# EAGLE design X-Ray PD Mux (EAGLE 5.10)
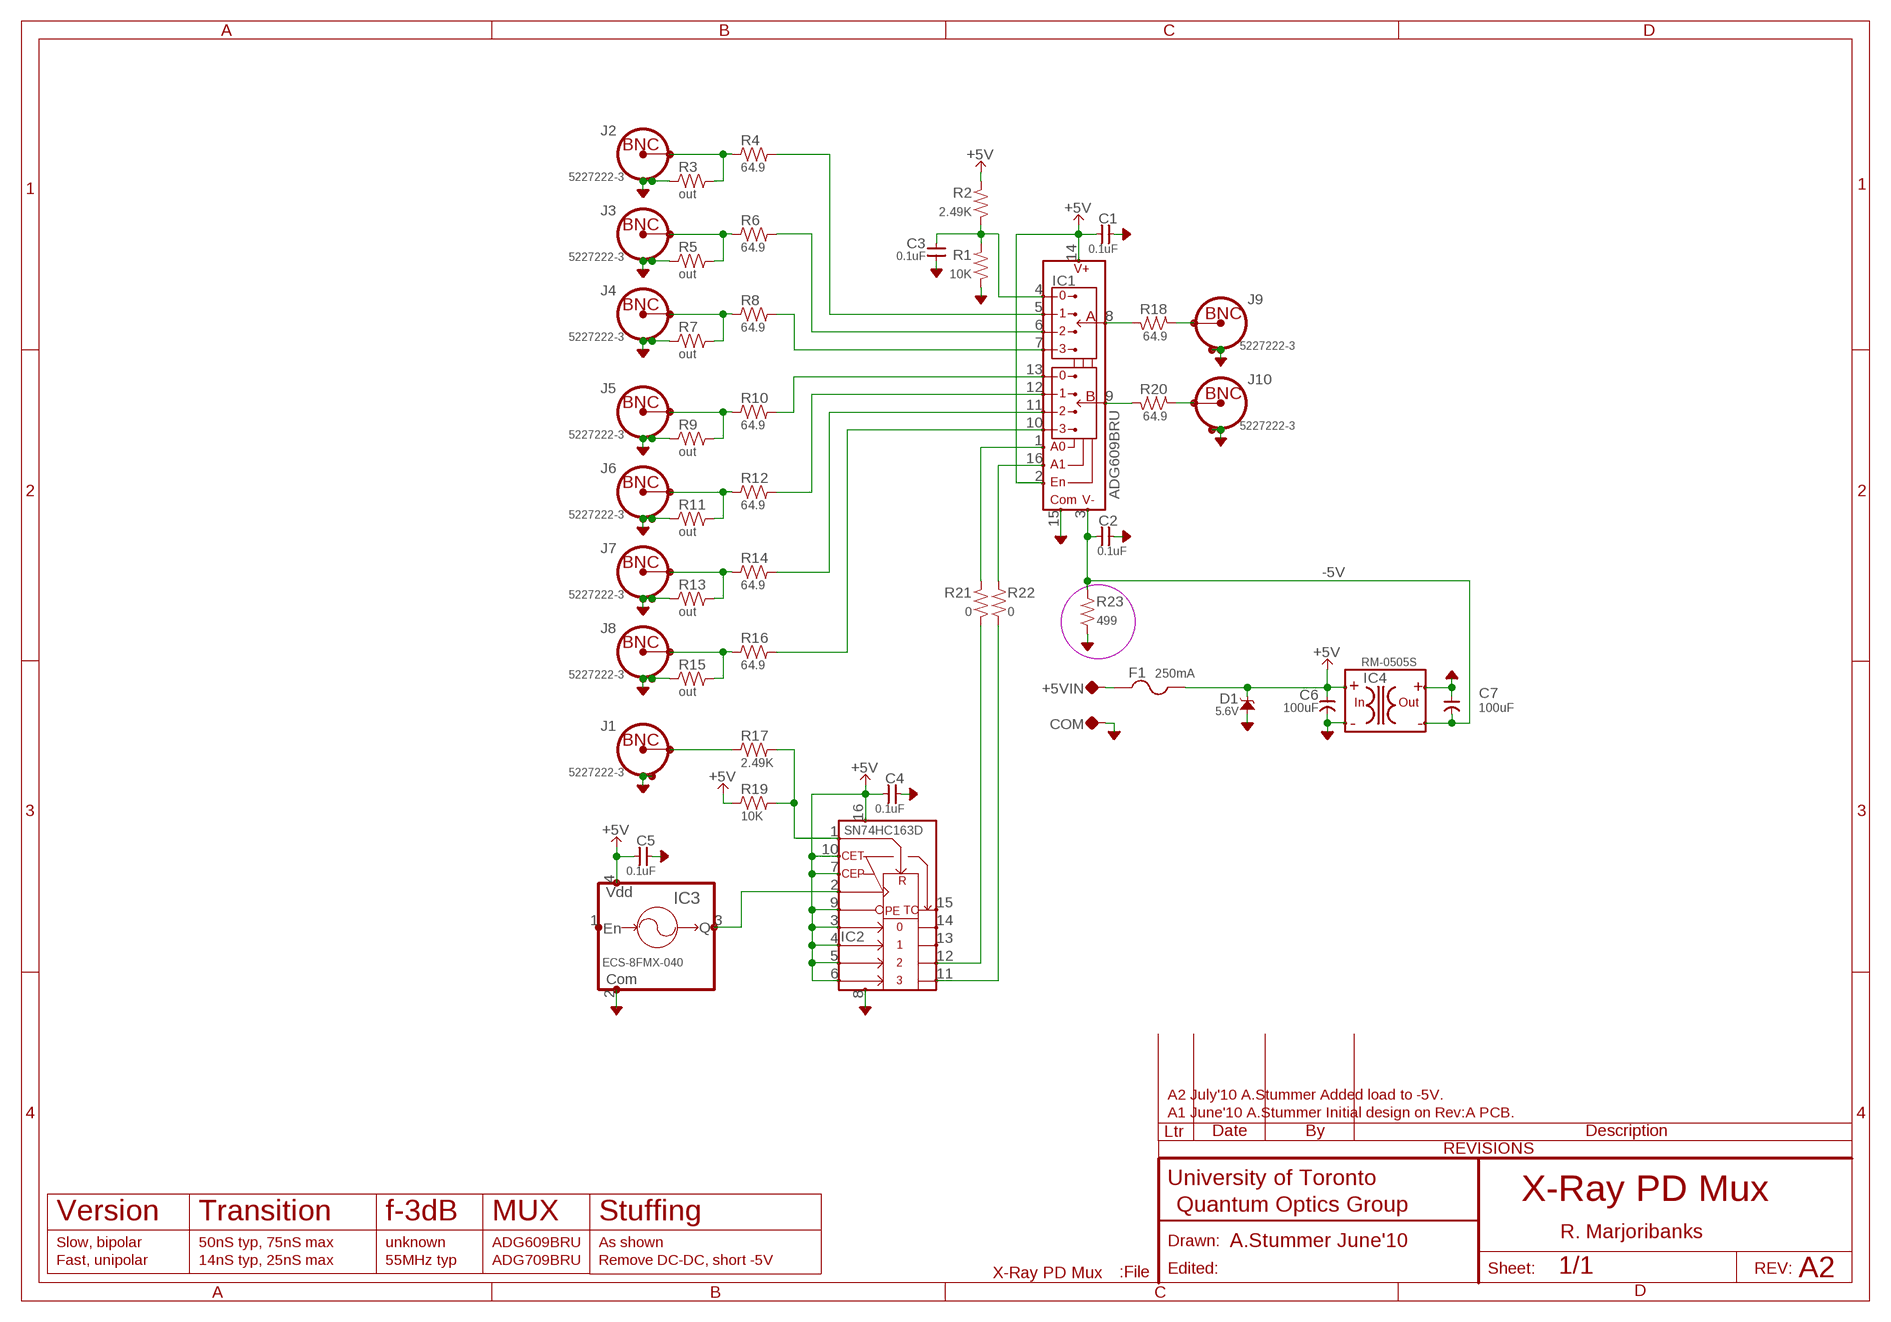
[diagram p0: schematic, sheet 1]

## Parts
+5VIN  TP-0.042B  [TP-0.042B]
C1  0.1uF  CAP-H-0805  [2012(0805)]
C2  0.1uF  CAP-H-0805  [2012(0805)]
C3  0.1uF  CAP-V-0805  [2012(0805)]
C4  0.1uF  CAP-H-0805  [2012(0805)]
C5  0.1uF  CAP-H-0805  [2012(0805)]
C6  100uF  CAP-POL--NIPPONCHEM_E61  [CAP:NIPPONCHEM_E61]
C7  100uF  CAP-POL--NIPPONCHEM_E61  [CAP:NIPPONCHEM_E61]
COM  TP-0.042B  [TP-0.042B]
D1  5.6V  ZENER-DFLZ  [ZENER:DFLZ_V_(1W)]
F1  250mA  FUSE-THROUGHHOLE  [PASSIVE_0.4"]
IC1  ADG609BRU  ANALOG,MUX:ADG609/709(DUAL4-CH)-TSSOP16(_RU)  [TSSOP-16]
IC2  SN74HC163D  LOGIC,COUNTER:74AC161/3(4-BIT)-SOIC16  [SOIC-16]
IC3  ECS-8FMX-040  OSCILLATOR:CX750(CITIZEN)-ECS8FX  [ECS8FX-OSC(ECS_INC)]
IC4  RM-0505S  DC-DC:GENERIC-ISO-UNI-RECOM_RM-XXXXS  [DC-DC:RECOM_RM-XXXXS]
J1  5227222-3  CONN-BNC-TYPE1VERT  [CONN-BNC-AMP-TYPE1VERT]
J2  5227222-3  CONN-BNC-TYPE1VERT  [CONN-BNC-AMP-TYPE1VERT]
J3  5227222-3  CONN-BNC-TYPE1VERT  [CONN-BNC-AMP-TYPE1VERT]
J4  5227222-3  CONN-BNC-TYPE1VERT  [CONN-BNC-AMP-TYPE1VERT]
J5  5227222-3  CONN-BNC-TYPE1VERT  [CONN-BNC-AMP-TYPE1VERT]
J6  5227222-3  CONN-BNC-TYPE1VERT  [CONN-BNC-AMP-TYPE1VERT]
J7  5227222-3  CONN-BNC-TYPE1VERT  [CONN-BNC-AMP-TYPE1VERT]
J8  5227222-3  CONN-BNC-TYPE1VERT  [CONN-BNC-AMP-TYPE1VERT]
J9  5227222-3  CONN-BNC-TYPE1VERT  [CONN-BNC-AMP-TYPE1VERT]
J10  5227222-3  CONN-BNC-TYPE1VERT  [CONN-BNC-AMP-TYPE1VERT]
R1  10K  R-V-0805  [2012(0805)]
R2  2.49K  R-V-0805  [2012(0805)]
R3  out  R-H-0805  [2012(0805)]
R4  64.9  R-H-0805  [2012(0805)]
R5  out  R-H-0805  [2012(0805)]
R6  64.9  R-H-0805  [2012(0805)]
R7  out  R-H-0805  [2012(0805)]
R8  64.9  R-H-0805  [2012(0805)]
R9  out  R-H-0805  [2012(0805)]
R10  64.9  R-H-0805  [2012(0805)]
R11  out  R-H-0805  [2012(0805)]
R12  64.9  R-H-0805  [2012(0805)]
R13  out  R-H-0805  [2012(0805)]
R14  64.9  R-H-0805  [2012(0805)]
R15  out  R-H-0805  [2012(0805)]
R16  64.9  R-H-0805  [2012(0805)]
R17  2.49K  R-H-0805  [2012(0805)]
R18  64.9  R-H-0805  [2012(0805)]
R19  10K  R-H-0805  [2012(0805)]
R20  64.9  R-H-0805  [2012(0805)]
R21  0  R-V-0805  [2012(0805)]
R22  0  R-V-0805  [2012(0805)]
R23  499  R-V-0805  [2012(0805)]

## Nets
+5V: C1.1 C4.1 C5.1 C6.POS D1.C F1.2(2A) IC1.2(EN) IC1.14(VDD) IC2.3(P0) IC2.4(P1) IC2.5(P2) IC2.6(P3) IC2.7(CEP) IC2.9(~PE) IC2.10(CET) IC2.16(VCC) IC3.4(VDD) IC4.2(IN+) R2.2 R19.1
-5V: C2.1 C7.NEG IC1.3(VSS) IC4.3(OUT-) R23.2
AGND: C1.2 C2.2 C3.1 C4.2 C5.2 C6.NEG C7.POS COM.TP D1.A IC1.15(COM) IC2.8(COM) IC3.2(COM) IC4.1(IN-) IC4.4(OUT+) J1.SHIELD1 J1.SHIELD2 J2.SHIELD1 J2.SHIELD2 J3.SHIELD1 J3.SHIELD2 J4.SHIELD1 J4.SHIELD2 J5.SHIELD1 J5.SHIELD2 J6.SHIELD1 J6.SHIELD2 J7.SHIELD1 J7.SHIELD2 J8.SHIELD1 J8.SHIELD2 J9.SHIELD1 J9.SHIELD2 J10.SHIELD1 J10.SHIELD2 R1.1 R3.1 R5.1 R7.1 R9.1 R11.1 R13.1 R15.1 R23.1
N$1: IC2.2(CLK) IC3.3(Q)
N$2: J2.CONDUCTOR R3.2 R4.1
N$3: J3.CONDUCTOR R5.2 R6.1
N$4: J4.CONDUCTOR R7.2 R8.1
N$5: J5.CONDUCTOR R9.2 R10.1
N$6: J6.CONDUCTOR R11.2 R12.1
N$7: J7.CONDUCTOR R13.2 R14.1
N$8: J8.CONDUCTOR R15.2 R16.1
N$9: IC1.13(S1B) R10.2
N$10: IC1.12(S2B) R12.2
N$11: IC1.11(S3B) R14.2
N$12: IC1.10(S4B) R16.2
N$13: IC1.7(S4A) R8.2
N$14: IC1.6(S3A) R6.2
N$15: IC1.5(S2A) R4.2
N$16: C3.2 IC1.4(S1A) R1.2 R2.1
N$17: J9.CONDUCTOR R18.1
N$18: J10.CONDUCTOR R20.1
N$19: IC1.8(DA) R18.2
N$20: IC1.9(DB) R20.2
N$21: IC2.11(Q3) R22.1
N$22: IC2.12(Q2) R21.1
N$23: IC2.1(~RST) R17.2 R19.2
N$24: +5VIN.TP F1.1(1A)
N$25: J1.CONDUCTOR R17.1
N$26: IC1.16(A1) R22.2
N$27: IC1.1(A0) R21.2
Unconnected: IC2.13(Q1) IC2.14(Q0) IC2.15(TC) IC3.1(EN)

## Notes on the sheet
- A2 July'10 A.Stummer Added load to -5V.
- A1 June'10 A.Stummer Initial design on Rev:A PCB.
- X-Ray PD Mux
- Version | Transition | f-3dB | MUX | Stuffing
- R. Marjoribanks
- Slow, bipolar | 50nS typ, 75nS max | unknown | ADG609BRU | As shown | A.Stummer June'10
- Fast, unipolar | 14nS typ, 25nS max | 55MHz typ | ADG709BRU | Remove DC-DC, short -5V
- A2

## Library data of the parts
+5VIN COM = QuantumOptics:TP: Testpoint, either SMT pad, small hole or loop style TP such as Keystone 5002K (0.042").
C1 C2 C4 C5 = QuantumOptics:CAP-H-: Cap, SMT and Through-hole, 0402 and up.
C3 = QuantumOptics:CAP-V-: Cap, SMT and Through-hole, 0402 and up.
C6 C7 = QuantumOptics:CAP-POL-: Capacitor, Polarized, SMT 0805 and up, probably tantalum.
D1 = QuantumOptics:ZENER: Zener
F1 = QuantumOptics:FUSE: Fuse
IC1 = QuantumOptics:ANALOG,MUX:ADG609/709(DUAL4-CH): Dual 4-channel analog mux, ADG609/709, http://www.analog.com/static/imported-files/data_sheets/ADG608_609.pdf
IC2 = QuantumOptics:LOGIC,COUNTER:74AC161/3(4-BIT): Counter, 74AC(T)161/3, 4-bit, fast, CMOS (AC) or TTL (ACT), sync load (161) or async (163). http://www.fairchildsemi.com/ds/74/74AC161.pdf
IC3 = QuantumOptics:OSCILLATOR:CX750(CITIZEN): CSX750 Oscillators, Citizen, +3.3V or +5V, 1MHZ to 133MHz. http://www.citizencrystal.com/images/pdf/os-csx750f.pdf
IC4 = QuantumOptics:DC-DC:GENERIC-ISO-UNI: DC-DC convertor, generic, unipolar, isolated.
J1-J10 = QuantumOptics:CONN-BNC: BNC PCB, horizontal or vertical, e.g. Horiz: Amp (5)227677-1, nut 1-329631-2, shoulder washer 330620. The two shield connections allow the assembly on either side of the board. Vert isolated: 5227222-6, http://catalog.tycoelectronics.com/TE/bin/TE.Connect?C=1&M=BYPN&TCPN=5227222-6&RQPN=5227222-6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; DESC: Input?
R1 R2 R21-R23 = QuantumOptics:R-V-*: Resistor, SMT & Through-Hole, vertical symbol
R3-R20 = QuantumOptics:R-H-*: Resistor, SMT & Through-Hole, horizontal symbol

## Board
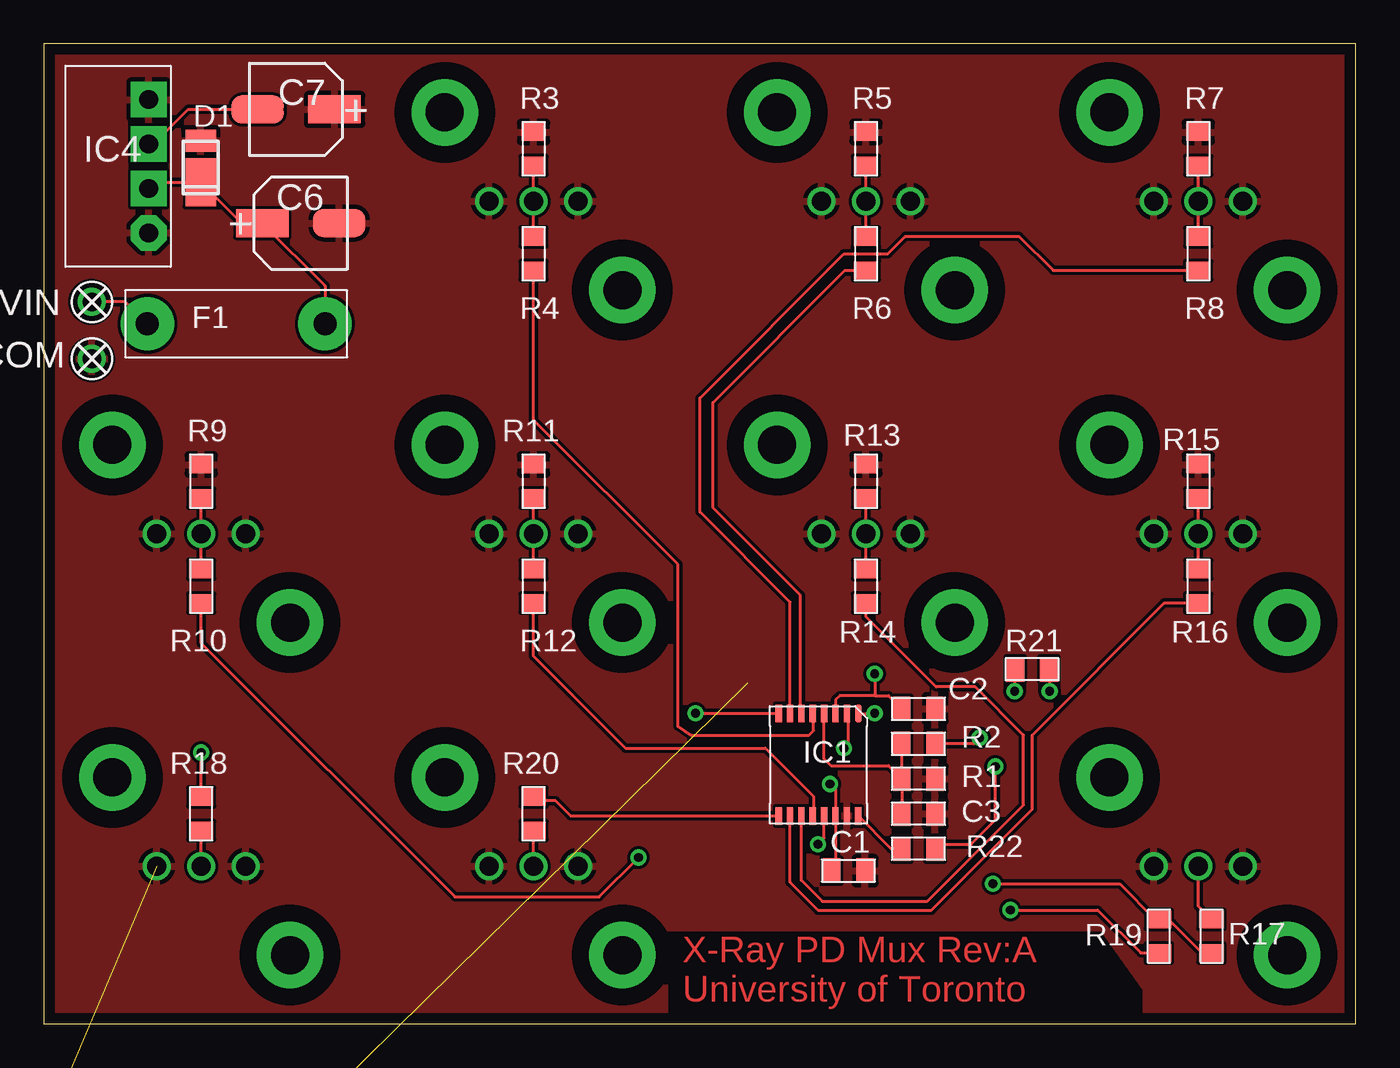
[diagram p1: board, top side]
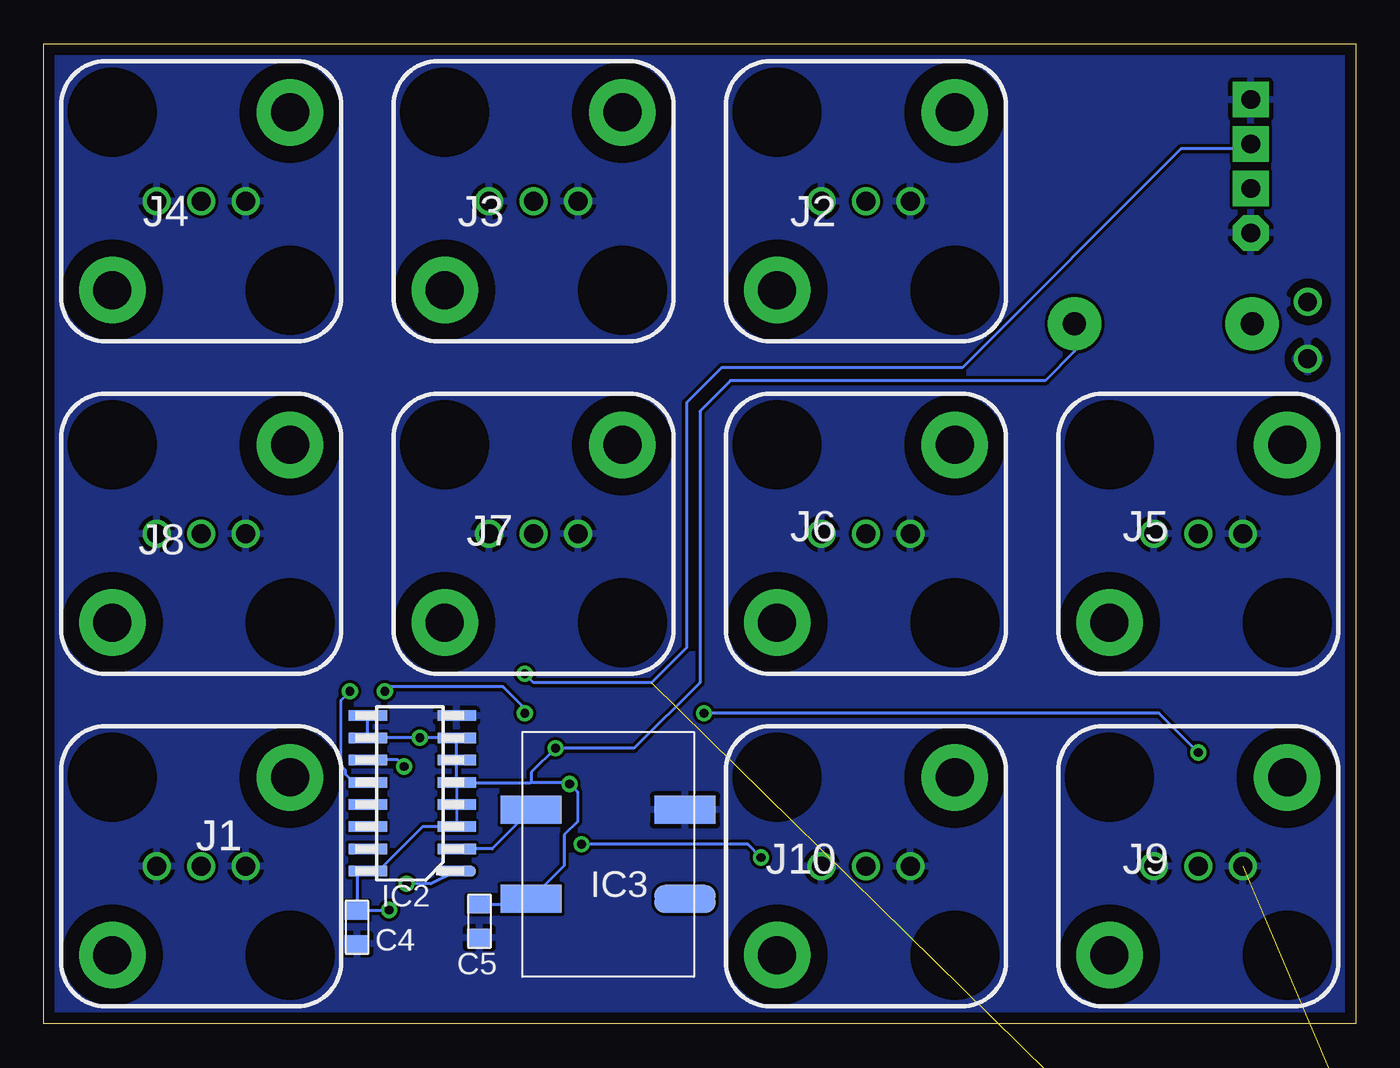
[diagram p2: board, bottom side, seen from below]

Size 75 x 56 mm. Coordinates in mm from the lower left corner, seen from the top.
Outline: 0,0 75,0 75,56 0,56 0,0
Copper layers (1+16): Top 0.035mm / dielectric 1.5mm / Bottom 0.035mm
Design rules "DRC standard check": minimum track width 7mil, minimum drill 20mil, track to track 7mil, track to pad 7mil, pad to pad 7mil, via to via 7mil, smd to smd 0mil, copper to edge 25mil, drill to drill 8mil, minimum pad ring 10mil, minimum via ring 8mil, stop-mask expansion 4mil, vias tented up to drill 0mil, thermal gap 10mil
Holes 12.7 mm at 134.75,14 153.75,14 191.75,14 134.75,33 172.75,33 153.75,33 191.75,33 191.75,52 172.75,52 153.75,52
Holes 3 mm at 118.2,8.2 118.2,57.8 208.3,57.8 208.3,8.2

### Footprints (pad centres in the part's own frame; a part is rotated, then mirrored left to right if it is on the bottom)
TP-0.042B = drill 1.067 round: TP 0,0
2012(0805) = smd 1.016 x 1.397: 1 -0.953,0; 2 0.953,0
CAP:NIPPONCHEM_E61 = smd 3 x 1.6: NEG -2.2,0; POS 2.2,0
ZENER:DFLZ_V_(1W) = smd 1.25 x 1.75: A -1.525,0 | smd 2.75 x 1.75: C 0.85,0
PASSIVE_0.4" = drill 1.321 pad 3.048 round: 1 -5.08,0; 2 5.08,0
TSSOP-16 = smd 0.356 x 1.016: 1 -1.95,-2.925; 2 -1.3,-2.925; 3 -0.65,-2.925; 4 0,-2.925; 5 0.65,-2.925; 6 1.3,-2.925; 7 1.95,-2.925; 8 2.6,-2.925; 9 2.6,2.925; 10 1.95,2.925; 11 1.3,2.925; 12 0.65,2.925; 13 0,2.925; 14 -0.65,2.925; 15 -1.3,2.925; 16 -1.95,2.925
SOIC-16 = smd 0.6 x 2.2: 1 -3.81,-2.54; 2 -2.54,-2.54; 3 -1.27,-2.54; 4 0,-2.54; 5 1.27,-2.54; 6 2.54,-2.54; 7 3.81,-2.54; 8 5.08,-2.54; 9 5.08,2.54; 10 3.81,2.54; 11 2.54,2.54; 12 1.27,2.54; 13 0,2.54; 14 -1.27,2.54; 15 -2.54,2.54; 16 -3.81,2.54
ECS8FX-OSC(ECS_INC) = smd 1.6 x 3.5: 1 -2.54,-4.4; 2 2.54,-4.4; 3 2.54,4.4; 4 -2.54,4.4
DC-DC:RECOM_RM-XXXXS = drill 1.067 pad 2.032 octagon: 1 -3.81,0 | drill 1.067 pad 2.032 square: 2 -1.27,0; 3 1.27,0; 4 3.81,0
CONN-BNC-AMP-TYPE1VERT = drill 1.067 round: CONDUCTOR 0,0; SHIELD1 -2.54,0; SHIELD2 2.54,0 | drill 2.184 pad 3.81 round: MTG1 -5.08,-5.08; MTG2 5.08,5.08

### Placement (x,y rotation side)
+5VIN  2.75,41.25 180 top
C1  46,8.75 0 top
C2  50,18 0 top
C3  50,12 180 top
C4  57.1,5.51 270 bottom
C5  50.1,5.86 270 bottom
C6  14.69,45.75 180 top
C7  14.42,52.25 0 top
COM  2.75,38 270 top
D1  8.98,48.93 270 top
F1  11,40 0 top
IC1  44.61,14.8 180 top
IC2  53.94,12.53 90 bottom
IC3  42.74,9.68 90 bottom
IC4  6,49 90 top
J1  66,9 0 bottom
J2  28,47 0 bottom
J3  47,47 0 bottom
J4  66,47 0 bottom
J5  9,28 0 bottom
J6  28,28 0 bottom
J7  47,28 0 bottom
J8  66,28 0 bottom
J9  9,9 0 bottom
J10  28,9 0 bottom
R1  50,14 180 top
R2  50,16 0 top
R3  28,50 270 top
R4  28,44 270 top
R5  47,50 270 top
R6  47,44 270 top
R7  66,50 270 top
R8  66,44 270 top
R9  9,31 270 top
R10  9,25 270 top
R11  28,31 270 top
R12  28,25 270 top
R13  47,31 270 top
R14  47,25 270 top
R15  66,31 270 top
R16  66,25 270 top
R17  66.75,5 270 top
R18  9,12 90 top
R19  63.75,5 90 top
R20  28,12 90 top
R21  56.5,20.25 180 top
R22  50,10 180 top
R23  not placed on the board
U$24  [TITLEBLOCK_PCB]  0,-2 0 top

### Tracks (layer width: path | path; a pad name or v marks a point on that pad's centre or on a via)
+5V  (via drill 0.51)
  Top 0.178: F1.2 16.08,42.16 C6.POS 11.31,45.75 D1.C 6.35,48.08 IC4.2 | v45.75,15.75 46,16 46,17.64 IC1.2 | R2.2 53.16,16 v53.5,16.34 | C1.1 45.25,9.3 45.25,11.87 IC1.14 45.25,13.4 v44.95,13.7 | R19.1 62.7,4.05 60.25,6.5 v55.25,6.5
  Bottom 0.178: F1.2 16.08,38.42 17.75,36.75 35.75,36.75 37.5,35 37.5,19.5 41.25,15.75 v45.75,15.75 47.14,14.36 47.14,13.8 | C5.1 47.47,6.81 IC3.4 45.25,9.03 45.25,10.8 44.5,11.55 44.5,13.25 v44.95,13.7 45.05,13.8 47.14,13.8 | IC2.16 56.03,8.72 | IC2.16 57.1,8.59 C4.1 57.06,6.5 v55.25,6.5 | IC2.9 IC2.10 v53.5,16.34 IC2.7 IC2.6 IC2.5 | IC2.5 IC2.4 IC2.3 52.16,11.25 53.35,11.25 55.8,8.8 56.4,8.8 IC2.16 | IC2.5 51.35,13.75 47.19,13.75 47.14,13.8
-5V  (via drill 0.51)  (1 unrouted)
  Top 0.178: C7.NEG 8.25,52.25 6.27,50.27 IC4.3 | IC1.3 45.26,18.51 45.5,18.75 47.5,18.75 | 47.5,18.75 48.3,18.75 C2.1 | v47.5,20 47.5,18.75
  Bottom 0.178: v47.5,20 47,19.5 40.25,19.5 38.25,21.5 38.25,35.5 36.25,37.5 22.5,37.5 10,50 6.25,50 6.25,50.02 IC4.3
AGND  (1 unrouted)
  pour Bottom (rank 2): 0,0 75,0 75,56 0,56
  pour Top (rank 2): 0,0 35.5,0 35.5,5.5 60.5,5.5 63,2 63,0 75,0 75,56 0,56
N$1
  Bottom 0.178: IC2.2 49.37,9.99 IC3.3
N$2
  Top 0.178: R4.1 J2.CONDUCTOR R3.2
N$3
  Top 0.178: R5.2 J3.CONDUCTOR R6.1
N$4
  Top 0.178: R8.1 J4.CONDUCTOR R7.2
N$5
  Top 0.178: R9.2 J5.CONDUCTOR R10.1
N$6
  Top 0.178: R12.1 J6.CONDUCTOR R11.2
N$7
  Top 0.178: R14.1 J7.CONDUCTOR R13.2
N$8
  Top 0.178: R16.1 J8.CONDUCTOR R15.2
N$9  (via drill 0.51)
  Top 0.178: R10.2 9,21.75 23.5,7.25 31.75,7.25 v34,9.5 | IC1.13 44.61,10.61 v44.25,10.25
  Bottom 0.178: v44.25,10.25 34.75,10.25 v34,9.5
N$10
  Top 0.178: R12.2 28,21 33.25,15.75 41.25,15.75 44,13 44,11.91 IC1.12
N$11
  Top 0.178: IC1.11 43.31,8.19 44.5,7 50.5,7 56,12.5 56,16.5 53.25,19.25 51,19.25 47,23.25 R14.2
N$12
  Top 0.178: IC1.10 42.66,8.09 44.25,6.5 50.75,6.5 56.5,12.25 56.5,16.5 64.05,24.05 R16.2
N$13
  Top 0.178: R8.2 57.7,43.05 55.75,45 49.25,45 48.25,44 45.75,44 37.5,35.75 37.5,29.25 42.66,24.09 IC1.7
N$14
  Top 0.178: R6.2 45.8,43.05 38.25,35.5 38.25,29.5 43.25,24.5 43.25,17.79 IC1.6
N$15
  Top 0.178: R4.2 28,34.5 36.25,26.25 36.25,17 37,16.5 43.75,16.5 44,16.75 44,17.68 IC1.5
N$16
  Top 0.178: R1.2 C3.2 | R1.2 R2.1 | IC1.4 44.61,15.14 45,14.75 48.3,14.75 R1.2
N$17
  Top 0.178: J9.CONDUCTOR R18.1
N$18
  Top 0.178: J10.CONDUCTOR R20.1
N$19  (via drill 0.51)
  Top 0.178: R18.2 v9,15.5 | v37.25,17.75 41.98,17.75 IC1.8
  Bottom 0.178: v37.25,17.75 11.25,17.75 v9,15.5
N$20
  Top 0.178: IC1.9 30.12,11.88 29.25,12.75 28.2,12.75 R20.2
N$21  (via drill 0.51)
  Top 0.178: v54.4,14.7 54.4,11.65 53,10.25 51.2,10.25 R22.1
  Bottom 0.178: v54.4,14.7 54.8,15.1 56.45,15.1 IC2.11
N$22  (via drill 0.51)
  Top 0.178: v57.5,19 57.5,20.2 R21.1
  Bottom 0.178: IC2.12 57.3,13.8 57.75,14.25 57.75,14.5 58,14.75 58,18.5 v57.5,19
N$23  (via drill 0.51)
  Top 0.178: R17.2 66.2,4.05 64.5,5.75 63.95,5.75 R19.2 63.55,5.95 61.5,8 v54.25,8
  Bottom 0.178: v54.25,8 52.87,8 IC2.1
N$24
  Top 0.178: +5VIN.TP 4.67,41.25 F1.1
N$25
  Top 0.178: J1.CONDUCTOR 66,6.7 R17.1
N$26
  Top 0.178: R22.2 48.44,10 IC1.16
N$27  (via drill 0.51)
  Top 0.178: IC1.1 47.48,17.73 v47.5,17.75 | v55.5,19 55.5,20.2 R21.2
  Bottom 0.178: v47.5,17.75 47.5,18 48.75,19.25 55.25,19.25 v55.5,19

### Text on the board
Top: X-Ray PD Mux Rev:A | University of Toronto
Document: Hammond 1594C drilling (inside view) | X-Ray PD MUX | A. Stummer June 2010 | A2 | 0.17mm | 0.17mm | 0.17mm | 0.25mm | Use case Hammond 1594C or Keystone 706.
Reference: (ref) | (ref) | 43.8 | 1/2" | 24.8 | 10 pl | 5.8 | (ref) | 0 | Datum | Mtg hole | 0 | 16.55 | 35.55 | 54.55 | 73.55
